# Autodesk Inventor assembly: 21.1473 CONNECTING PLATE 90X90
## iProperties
Created: 2007-01
Part Number: 21.1473 CONNECTING PLATE 90X90
Document SubType Name: Assembly
Designer: Andy Moles
Author: Andy Moles
